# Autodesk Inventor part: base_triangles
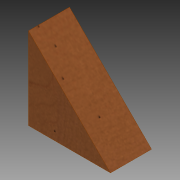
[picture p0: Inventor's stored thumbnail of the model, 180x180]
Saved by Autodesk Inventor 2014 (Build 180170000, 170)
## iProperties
Created: 2014-05
Part Number: base_triangles
Material: Maple
Document SubType Name: Modeling
Designer: t_emanb
Density: 0.705 g/cm^3
Appearance: Maple - Solid Natural Medium Gloss
Author: t_emanb
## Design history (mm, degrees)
sketch "Sketch1"
  geometry: L1 (0, 0)-(0, 76.2); L2 (0, 76.2)-(76.2, 0); L3 (76.2, 0)-(0, 0)
  constraints: 6 end point, 1 perpendicular, 1 vertical
  dimensions: "d0" = 76.2 distance of L2.end L1.start; "d1" = 76.2 distance of L1.start L1.end
extrude "Extrusion1" new body sketch "Sketch1" distance "d2" = 38.1; taper "d3" = 0 deg
body "Solid1"
